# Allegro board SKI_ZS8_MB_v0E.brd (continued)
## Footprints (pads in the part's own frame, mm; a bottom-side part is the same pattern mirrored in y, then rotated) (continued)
BSH-030-01-L-D-A-TR-60P-LDH
  round 1.016 hole 1.016 unplated: (-10.063,-2.666) (10.063,-2.666)
  rect 0.279x2.261 smd: 1(-7.25,-2.864) 2(-6.75,-2.864) 3(-6.25,-2.864) 4(-5.75,-2.864) 5(-5.25,-2.864) 6(-4.75,-2.864) 7(-4.25,-2.864) 8(-3.75,-2.864) 9(-3.25,-2.864) 10(-2.75,-2.864) 11(-2.25,-2.864) 12(-1.75,-2.864) 13(-1.25,-2.864) 14(-0.75,-2.864) 15(-0.25,-2.864) 16(0.25,-2.864) 17(0.75,-2.864) 18(1.25,-2.864) 19(1.75,-2.864) 20(2.25,-2.864) 21(2.75,-2.864) 22(3.25,-2.864) 23(3.75,-2.864) 24(4.25,-2.864) 25(4.75,-2.864) 26(5.25,-2.864) 27(5.75,-2.864) 28(6.25,-2.864) 29(6.75,-2.864) 30(7.25,-2.864) 31(7.25,2.864) 32(6.75,2.864) 33(6.25,2.864) 34(5.75,2.864) 35(5.25,2.864) 36(4.75,2.864) 37(4.25,2.864) 38(3.75,2.864) 39(3.25,2.864) 40(2.75,2.864) 41(2.25,2.864) 42(1.75,2.864) 43(1.25,2.864) 44(0.75,2.864) 45(0.25,2.864) 46(-0.25,2.864) 47(-0.75,2.864) 48(-1.25,2.864) 49(-1.75,2.864) 50(-2.25,2.864) 51(-2.75,2.864) 52(-3.25,2.864) 53(-3.75,2.864) 54(-4.25,2.864) 55(-4.75,2.864) 56(-5.25,2.864) 57(-5.75,2.864) 58(-6.25,2.864) 59(-6.75,2.864) 60(-7.25,2.864)
CC0402
  custom 0.12x0.12 smd: 1(0.39,0) 2(-0.39,0)
CC0603
  rect 0.813x0.711 smd: 1(0.737,0) 2(-0.737,0)
CC0805
  rect 0.94x1.346 smd: 1(0.895,0) 2(-0.895,0)
CC3528
  rect 2.032x2.413 smd: 1(1.6,0) 2(-1.6,0)
CC7343
  rect 2.413x2.819 smd: 1(-3.2,0) 2(3.2,0)
CHOKE-PCMC063T-3R3MN-SMT
  rect 1.854x3.505 smd: 1(-3.275,0) 2(3.275,0)
CHOKE-PCMC063T-R82MN-4P-SMT
  custom 0.591x0.591 smd: 1(-3.596,0) 2(3.596,0)
  rect 1.473x0.305 smd: 3(-2.452,0) 4(2.452,0)
D-DO-214AC
  rect 1.88x2.032 smd: 1(-2.1,0) 2(2.1,0)
DSM
  rect 1.016x0.508 smd: 1(-1.3,0) 2(1.321,0)
DSMV
  rect 1.016x0.762 smd: 1(-1.27,0) 2(1.27,0)
EMIPAD47X31-63X24-3P
  rect 1.6x0.61 smd: 1(-1.8,0) 3(1.8,0)
  rect 1.194x0.787 smd: 2(0,0)
EMIPAD63X56
  custom 0.358x0.358 smd: 1(0,0)
FILTER-MCM2012B900GBE-4P
  rect 0.762x0.406 smd: 1(-0.925,0.4) 2(0.925,0.4) 3(0.925,-0.4) 4(-0.925,-0.4)
H-C87D87N
  round 2.21 hole 2.21 unplated: (0,0)
H-C150D150N
  round 3.81 hole 3.81 unplated: (0,0)
H-C217D142P2
  round 5.512 hole 3.607: 1(0,0)
H-C236D102P2
  round 5.994 hole 2.591: 1(0,0)
H-O98X79D98X79N
  oval 2.489x2.007 hole 2.489x2.007 unplated: (0,0)
H-TC217BC165D165P2
  round 5.512 hole 4.191: 1(0,0)
H-TC236BC197D102P2
  round 5.994 hole 2.591: 1(0,0)
HDMI-C128F4-K1909-L-19P-SMT
  round 0.787 hole 0.559: 1(4.5,6.8) 2(4,5.3) 3(3.5,6.8) 4(3,5.3) 5(2.5,6.8) 6(2,5.3) 7(1.5,6.8) 8(1,5.3) 9(0.5,6.8) 10(0,5.3) 11(-0.5,6.8) 12(-1,5.3) 13(-1.5,6.8) 14(-2,5.3) 15(-2.5,6.8) 16(-3,5.3) 17(-3.5,6.8) 18(-4,5.3) 19(-4.5,6.8)
  oval 1.6x2.794 hole 1.092x2.311: 20(7.25,6.5) 22(-7.25,6.5)
  oval 1.6x1.905 hole 1.092x1.397: 21(8.75,0) 23(-8.75,0)
IMD
  rect 1.016x0.813 smd: 1(1.2,-1) 3(1.2,1) 4(-1.2,1) 6(-1.2,-1)
  rect 1.016x0.61 smd: 2(1.2,0) 5(-1.2,0)
LQFP128-16X16-4-1_6H
  rect 0.203x1.499 smd: 1(-6.2,-7.85) 2(-5.8,-7.85) 3(-5.4,-7.85) 4(-5,-7.85) 5(-4.6,-7.85) 6(-4.2,-7.85) 7(-3.8,-7.85) 8(-3.4,-7.85) 9(-3,-7.85) 10(-2.6,-7.85) 11(-2.2,-7.85) 12(-1.8,-7.85) 13(-1.4,-7.85) 14(-1,-7.85) 15(-0.6,-7.85) 16(-0.2,-7.85) 17(0.2,-7.85) 18(0.6,-7.85) 19(1,-7.85) 20(1.4,-7.85) 21(1.8,-7.85) 22(2.2,-7.85) 23(2.6,-7.85) 24(3,-7.85) 25(3.4,-7.85) 26(3.8,-7.85) 27(4.2,-7.85) 28(4.6,-7.85) 29(5,-7.85) 30(5.4,-7.85) 31(5.8,-7.85) 32(6.2,-7.85) 65(6.2,7.85) 66(5.8,7.85) 67(5.4,7.85) 68(5,7.85) 69(4.6,7.85) 70(4.2,7.85) 71(3.8,7.85) 72(3.4,7.85) 73(3,7.85) 74(2.6,7.85) 75(2.2,7.85) 76(1.8,7.85) 77(1.4,7.85) 78(1,7.85) 79(0.6,7.85) 80(0.2,7.85) 81(-0.2,7.85) 82(-0.6,7.85) 83(-1,7.85) 84(-1.4,7.85) 85(-1.8,7.85) 86(-2.2,7.85) 87(-2.6,7.85) 88(-3,7.85) 89(-3.4,7.85) 90(-3.8,7.85) 91(-4.2,7.85) 92(-4.6,7.85) 93(-5,7.85) 94(-5.4,7.85) 95(-5.8,7.85) 96(-6.2,7.85)
  rect 1.499x0.203 smd: 33(7.85,-6.2) 34(7.85,-5.8) 35(7.85,-5.4) 36(7.85,-5) 37(7.85,-4.6) 38(7.85,-4.2) 39(7.85,-3.8) 40(7.85,-3.4) 41(7.85,-3) 42(7.85,-2.6) 43(7.85,-2.2) 44(7.85,-1.8) 45(7.85,-1.4) 46(7.85,-1) 47(7.85,-0.6) 48(7.85,-0.2) 49(7.85,0.2) 50(7.85,0.6) 51(7.85,1) 52(7.85,1.4) 53(7.85,1.8) 54(7.85,2.2) 55(7.85,2.6) 56(7.85,3) 57(7.85,3.4) 58(7.85,3.8) 59(7.85,4.2) 60(7.85,4.6) 61(7.85,5) 62(7.85,5.4) 63(7.85,5.8) 64(7.85,6.2) 97(-7.85,6.2) 98(-7.85,5.8) 99(-7.85,5.4) 100(-7.85,5) 101(-7.85,4.6) 102(-7.85,4.2) 103(-7.85,3.8) 104(-7.85,3.4) 105(-7.85,3) 106(-7.85,2.6) 107(-7.85,2.2) 108(-7.85,1.8) 109(-7.85,1.4) 110(-7.85,1) 111(-7.85,0.6) 112(-7.85,0.2) 113(-7.85,-0.2) 114(-7.85,-0.6) 115(-7.85,-1) 116(-7.85,-1.4) 117(-7.85,-1.8) 118(-7.85,-2.2) 119(-7.85,-2.6) 120(-7.85,-3) 121(-7.85,-3.4) 122(-7.85,-3.8) 123(-7.85,-4.2) 124(-7.85,-4.6) 125(-7.85,-5) 126(-7.85,-5.4) 127(-7.85,-5.8) 128(-7.85,-6.2)
LVDS-50473-0200M-001-20P-L
  rect 0.254x1.092 smd: 1(-4.75,2.92) 2(-4.25,2.92) 3(-3.75,2.92) 4(-3.25,2.92) 5(-2.75,2.92) 6(-2.25,2.92) 7(-1.75,2.92) 8(-1.25,2.92) 9(-0.75,2.92) 10(-0.25,2.92) 11(0.25,2.92) 12(0.75,2.92) 13(1.25,2.92) 14(1.75,2.92) 15(2.25,2.92) 16(2.75,2.92) 17(3.25,2.92) 18(3.75,2.92) 19(4.25,2.92) 20(4.75,2.92)
  rect 0.559x1.092 smd: 21(-5.65,2.92) 22(5.65,2.92)
  rect 1.397x1.905 smd: 23(-7.85,0) 24(7.85,0)
LVDS-50473-0300M-V01-30P-L
  rect 0.254x1.092 smd: 1(-7.25,2.92) 2(-6.75,2.92) 3(-6.25,2.92) 4(-5.75,2.92) 5(-5.25,2.92) 6(-4.75,2.92) 7(-4.25,2.92) 8(-3.75,2.92) 9(-3.25,2.92) 10(-2.75,2.92) 11(-2.25,2.92) 12(-1.75,2.92) 13(-1.25,2.92) 14(-0.75,2.92) 15(-0.25,2.92) 16(0.25,2.92) 17(0.75,2.92) 18(1.25,2.92) 19(1.75,2.92) 20(2.25,2.92) 21(2.75,2.92) 22(3.25,2.92) 23(3.75,2.92) 24(4.25,2.92) 25(4.75,2.92) 26(5.25,2.92) 27(5.75,2.92) 28(6.25,2.92) 29(6.75,2.92) 30(7.25,2.92)
  rect 0.559x1.092 smd: 31(-8.15,2.92) 32(8.15,2.92)
  rect 1.397x1.905 smd: 33(-10.35,0) 34(10.35,0)
MINIPCI-SM3ZS067U215AE-75P-KE
  round 1.092 hole 1.092 unplated: (-10,0)
  round 1.6 hole 1.6 unplated: (10,0)
  rect 0.305x1.549 smd: 1(-9.25,5.225) 2(-9,-2.225) 3(-8.75,5.225) 4(-8.5,-2.225) 5(-8.25,5.225) 6(-8,-2.225) 7(-7.75,5.225) 8(-7.5,-2.225) 9(-7.25,5.225) 10(-7,-2.225) 11(-6.75,5.225) 12(-6.5,-2.225) 13(-6.25,5.225) 14(-6,-2.225) 15(-5.75,5.225) 16(-5.5,-2.225) 17(-5.25,5.225) 18(-5,-2.225) 19(-4.75,5.225) 20(-4.5,-2.225) 21(-4.25,5.225) 22(-4,-2.225) 23(-3.75,5.225) 32(-1.5,-2.225) 33(-1.25,5.225) 34(-1,-2.225) 35(-0.75,5.225) 36(-0.5,-2.225) 37(-0.25,5.225) 38(0,-2.225) 39(0.25,5.225) 40(0.5,-2.225) 41(0.75,5.225) 42(1,-2.225) 43(1.25,5.225) 44(1.5,-2.225) 45(1.75,5.225) 46(2,-2.225) 47(2.25,5.225) 48(2.5,-2.225) 49(2.75,5.225) 50(3,-2.225) 51(3.25,5.225) 52(3.5,-2.225) 53(3.75,5.225) 54(4,-2.225) 55(4.25,5.225) 56(4.5,-2.225) 57(4.75,5.225) 58(5,-2.225) 59(5.25,5.225) 60(5.5,-2.225) 61(5.75,5.225) 62(6,-2.225) 63(6.25,5.225) 64(6.5,-2.225) 65(6.75,5.225) 66(7,-2.225) 67(7.25,5.225) 68(7.5,-2.225) 69(7.75,5.225) 70(8,-2.225) 71(8.25,5.225) 72(8.5,-2.225) 73(8.75,5.225) 74(9,-2.225) 75(9.25,5.225)
  rect 1.194x2.743 smd: 76(-10.35,4.5) 77(10.35,4.5)
MSOP8-4_9-65
  rect 0.406x1.448 smd: 1(-0.975,-2.325) 2(-0.325,-2.325) 3(0.325,-2.325) 4(0.975,-2.325) 5(0.975,2.325) 6(0.325,2.325) 7(-0.325,2.325) 8(-0.975,2.325)
NGFF-80159-2181-75P-KM
  round 1.092 hole 1.092 unplated: (-11,0)
  round 1.6 hole 1.6 unplated: (11,0)
  round 0.762 hole 0.508: 1(9.25,-0.09) 3(8.75,-0.89) 5(8.25,-0.09) 7(7.75,-0.89) 9(7.25,-0.09) 11(6.75,-0.89) 13(6.25,-0.09) 15(5.75,-0.89) 17(5.25,-0.09) 19(4.75,-0.89) 21(4.25,-0.09) 23(3.75,-0.89) 25(3.25,-0.09) 27(2.75,-0.89) 29(2.25,-0.09) 31(1.75,-0.89) 33(1.25,-0.09) 35(0.75,-0.89) 37(0.25,-0.09) 39(-0.25,-0.89) 41(-0.75,-0.09) 43(-1.25,-0.89) 45(-1.75,-0.09) 47(-2.25,-0.89) 49(-2.75,-0.09) 51(-3.25,-0.89) 53(-3.75,-0.09) 55(-4.25,-0.89) 57(-4.75,-0.09) 67(-7.25,-0.89) 69(-7.75,-0.09) 71(-8.25,-0.89) 73(-8.75,-0.09) 75(-9.25,-0.89)
  rect 0.305x1.499 smd: 2(9,1.7) 4(8.5,1.7) 6(8,1.7) 8(7.5,1.7) 10(7,1.7) 12(6.5,1.7) 14(6,1.7) 16(5.5,1.7) 18(5,1.7) 20(4.5,1.7) 22(4,1.7) 24(3.5,1.7) 26(3,1.7) 28(2.5,1.7) 30(2,1.7) 32(1.5,1.7) 34(1,1.7) 36(0.5,1.7) 38(0,1.7) 40(-0.5,1.7) 42(-1,1.7) 44(-1.5,1.7) 46(-2,1.7) 48(-2.5,1.7) 50(-3,1.7) 52(-3.5,1.7) 54(-4,1.7) 56(-4.5,1.7) 58(-5,1.7) 68(-7.5,1.7) 70(-8,1.7) 72(-8.5,1.7) 74(-9,1.7)
  oval 0.889x1.956 hole 0.508x1.753: 76(11.25,-4.05) 77(-11.25,-4.05)
O-SKI-1
  round 5.994 hole 2.591: 1(0,0)
  oval 0.61x2.388 hole 0.61x2.388: 2(-9.55,-2.085) 3(23.25,-2.085)
PHJK-2SJ3095-033111F-6P
  oval 0.991x1.803 hole 0.61x1.397: 1(-4.85,7.01) 2(4.7,1.51) 3(-4.85,-0.79) 4(4.7,-1.39) 5(4.7,7.01) 6(4.7,4.26) 7(-4.85,2.91)
POWER-6_5-1_84-3P
  rect 0.787x1.397 smd: 1(3.532,0.9) 2(3.532,-0.9)
  rect 4.699x3.607 smd: 3(-0.338,0)
PVQFN20-3_5X3_5-5-25P
  rect 0.279x0.838 smd: 1(-1,-1.725) 2(-0.5,-1.725) 3(0,-1.725) 4(0.5,-1.725) 5(1,-1.725) 11(1,1.725) 12(0.5,1.725) 13(0,1.725) 14(-0.5,1.725) 15(-1,1.725)
  rect 0.838x0.279 smd: 6(1.725,-1) 7(1.725,-0.5) 8(1.725,0) 9(1.725,0.5) 10(1.725,1) 16(-1.725,1) 17(-1.725,0.5) 18(-1.725,0) 19(-1.725,-0.5) 20(-1.725,-1)
  rect 2.057x2.057 smd: 21(0,0)
  round 0.61 hole 0.305: 22(-0.5,-0.5) 23(0.5,-0.5) 24(0.5,0.5) 25(-0.5,0.5)
QFN14-3X3-4-16P
  rect 1.092x0.203 smd: 1(-1.25,0.525) 2(-1.25,-0.175) 8(1.25,-0.525) 9(1.25,0.175)
  rect 0.203x0.711 smd: 3(-0.8,-1.45) 4(-0.4,-1.45) 5(0,-1.45) 6(0.4,-1.45) 7(0.8,-1.45) 10(0.8,1.45) 11(0.4,1.45) 12(0,1.45) 13(-0.4,1.45) 14(-0.8,1.45)
  rect 0.66x0.203 smd: 15(0,0.165) 16(0,-0.435)
QFN20-3X3-4-26P
  rect 0.787x0.203 smd: 1(-1.5,0.8) 2(-1.5,0.4) 3(-1.5,0) 4(-1.5,-0.4) 5(-1.5,-0.8) 11(1.5,-0.8) 12(1.5,-0.4) 13(1.5,0) 14(1.5,0.4) 15(1.5,0.8)
  rect 0.203x0.787 smd: 6(-0.8,-1.5) 7(-0.4,-1.5) 8(0,-1.5) 9(0.4,-1.5) 10(0.8,-1.5) 16(0.8,1.5) 17(0.4,1.5) 18(0,1.5) 19(-0.4,1.5) 20(-0.8,1.5)
  rect 1.803x1.803 smd: 21(0,0)
  round 0.508 hole 0.305: 22(-0.5,0.5) 23(-0.5,-0.5) 24(0.5,-0.5) 25(0.5,0.5) 26(0,0)
QFN32-4X4-4-42P-1H
  custom 0.05x0.05 smd: 1(-2,1.4) 2(-2,1) 3(-2,0.6) 4(-2,0.2) 5(-2,-0.2) 6(-2,-0.6) 7(-2,-1) 8(-2,-1.4) 9(-1.4,-2) 10(-1,-2) 11(-0.6,-2) 12(-0.2,-2) 13(0.2,-2) 14(0.6,-2) 15(1,-2) 16(1.4,-2) 17(2,-1.4) 18(2,-1) 19(2,-0.6) 20(2,-0.2) 21(2,0.2) 22(2,0.6) 23(2,1) 24(2,1.4) 25(1.4,2) 26(1,2) 27(0.6,2) 28(0.2,2) 29(-0.2,2) 30(-0.6,2) 31(-1,2) 32(-1.4,2)
  rect 2.794x2.794 smd: 33(0,0)
  round 0.61 hole 0.305: 34(-1,1) 35(-1,0) 36(-1,-1) 37(0,-1) 38(1,-1) 39(1,0) 40(1,1) 41(0,1) 42(0,0)
QFN48-6X6-4-49P-ALC280
  rect 0.203x0.991 smd: 1(-2.2,-3.1) 2(-1.8,-3.1) 3(-1.4,-3.1) 4(-1,-3.1) 5(-0.6,-3.1) 6(-0.2,-3.1) 7(0.2,-3.1) 8(0.6,-3.1) 9(1,-3.1) 10(1.4,-3.1) 11(1.8,-3.1) 12(2.2,-3.1) 25(2.2,3.1) 26(1.8,3.1) 27(1.4,3.1) 28(1,3.1) 29(0.6,3.1) 30(0.2,3.1) 31(-0.2,3.1) 32(-0.6,3.1) 33(-1,3.1) 34(-1.4,3.1) 35(-1.8,3.1) 36(-2.2,3.1)
  rect 0.991x0.203 smd: 13(3.1,-2.2) 14(3.1,-1.8) 15(3.1,-1.4) 16(3.1,-1) 17(3.1,-0.6) 18(3.1,-0.2) 19(3.1,0.2) 20(3.1,0.6) 21(3.1,1) 22(3.1,1.4) 23(3.1,1.8) 24(3.1,2.2) 37(-3.1,2.2) 38(-3.1,1.8) 39(-3.1,1.4) 40(-3.1,1) 41(-3.1,0.6) 42(-3.1,0.2) 43(-3.1,-0.2) 44(-3.1,-0.6) 45(-3.1,-1) 46(-3.1,-1.4) 47(-3.1,-1.8) 48(-3.1,-2.2)
  rect 4.394x4.394 smd: 49(0,0)
RC0402
  custom 0.12x0.12 smd: 1(0.39,0) 2(-0.39,0)
RC0603
  rect 0.813x0.711 smd: 1(0.737,0) 2(-0.737,0)
RC0805
  rect 0.94x1.346 smd: 1(0.895,0) 2(-0.895,0)
RC1206
  rect 1.6x1.6 smd: 1(1.702,0) 2(-1.702,0)
RC3216
  rect 3.2x0.94 smd: 1(0,0.825) 2(0,-0.825)
SC70-2_1-65-6P
  rect 1.27x0.279 smd: 1(1.02,-0.65) 2(1.02,0) 3(1.02,0.65) 4(-1.02,0.65) 5(-1.02,0) 6(-1.02,-0.65)
SHORT0402
  rect 0.648x0.5 smd: 1(-0.39,0) 2(0.39,0)
SHORT0603
  rect 1.168x0.711 smd: 1(0.737,0) 2(-0.737,0)
SHORT0805
  rect 1.397x1.346 smd: 1(0.895,0) 2(-0.895,0)
SHORT3720
  rect 3.759x1.537 smd: 1(0,1.008) 2(0,-1.008)
SO-8FL-5P-OA
  rect 0.991x0.762 smd: 1(3.73,-1.905) 2(3.73,-0.635) 3(3.73,0.635) 4(3.73,1.905)
  custom 1.132x1.132 smd: 5(0,0)
SOIC8-6-1_27
  rect 0.533x1.753 smd: 1(-1.905,-2.73) 2(-0.635,-2.73) 3(0.635,-2.73) 4(1.905,-2.73) 5(1.905,2.73) 6(0.635,2.73) 7(-0.635,2.73) 8(-1.905,2.73)
SOIC8-7_9-1_27-2_16H
  rect 0.533x1.549 smd: 1(-1.905,-3.775) 2(-0.635,-3.775) 3(0.635,-3.775) 4(1.905,-3.775) 5(1.905,3.775) 6(0.635,3.775) 7(-0.635,3.775) 8(-1.905,3.775)
SOLDERJUMPER-2
  custom 0.381x0.381 smd: 1(-1.016,0) 2(1.016,0)
SON8-4_5X3_5-5-9P-SMT
  custom 0.05x0.05 smd: 1(-1.6,-1.6) 2(-1.2,-1.6) 3(-0.8,-1.6) 6(-0.8,1.6) 7(-1.2,1.6) 8(-1.6,1.6)
  custom 0.188x0.188 smd: 4(0.6,-1.6) 5(0.6,1.6)
  rect 4.039x2.21 smd: 9(0,0)
SON10-3X3-5-16P
  rect 0.279x0.838 smd: 1(-1,-1.475) 2(-0.5,-1.475) 3(0,-1.475) 4(0.5,-1.475) 5(1,-1.475) 6(1,1.475) 7(0.5,1.475) 8(0,1.475) 9(-0.5,1.475) 10(-1,1.475)
  custom 0.413x0.413 smd: 11(0,0)
  round 0.61 hole 0.305: 12(-0.75,-0.5) 13(0.75,-0.5) 14(0.75,0.5) 15(-0.75,0.5) 16(0,0)
SOP8-6-1_27-9P
  rect 0.533x1.727 smd: 1(-1.905,-2.73) 2(-0.635,-2.73) 3(0.635,-2.73) 4(1.905,-2.73) 5(1.905,2.73) 6(0.635,2.73) 7(-0.635,2.73) 8(-1.905,2.73)
  rect 3.302x2.794 smd: 9(0,0)
SOT23-2_8-95-6P
  rect 1.346x0.508 smd: 1(1.325,-0.95) 2(1.325,0) 3(1.325,0.95) 4(-1.325,0.95) 5(-1.325,0) 6(-1.325,-0.95)
SOT23-6-2_8-95-6P
  rect 1.194x0.508 smd: 1(1.5,-0.95) 2(1.5,0) 3(1.5,0.95) 4(-1.5,0.95) 5(-1.5,0) 6(-1.5,-0.95)
SOT23_123-2_8-1_9
  rect 1.092x0.533 smd: 1(1.45,-0.95) 2(1.45,0.95) 3(-1.45,0)
SOT23_213-3_3-2
  rect 1.27x1.016 smd: 1(1.016,1.016) 2(1.016,-1.016) 3(-1.016,0)
SOT353-1-2_125-65-5P
  rect 1.245x0.279 smd: 1(1.045,-0.65) 2(1.045,0) 3(1.045,0.65) 4(-1.045,0.65) 5(-1.045,-0.65)
SSOP5-P-A-TOSHIBA-B
  rect 1.067x0.305 smd: 1(0.85,-0.65) 2(0.85,0) 3(0.85,0.65) 4(-0.85,0.65) 5(-0.85,-0.65)
SW-NTC017-BB1J-X160T-4P-SMT
  rect 0.61x0.991 smd: 1(-1.85,2.2) 2(1.85,2.2) 3(-1.85,-2.2) 4(1.85,-2.2)
  rect 0.457x1.499 smd: 5(-2.525,0) 6(2.525,0)
SW-TC901-AA1G-A160T-6P
  rect 0.991x1.702 smd: 1(-1.8,3.15) 2(1.8,3.15) 3(-1.8,-3.15) 4(1.8,-3.15)
  rect 0.457x0.991 smd: 5(-2.525,0) 6(2.525,0)
TDFN8-2X2-5-9P-MAX14566
  rect 0.305x0.711 smd: 1(-0.75,-0.99) 2(-0.25,-0.99) 3(0.25,-0.99) 4(0.75,-0.99) 5(0.75,0.99) 6(0.25,0.99) 7(-0.25,0.99) 8(-0.75,0.99)
  rect 1.295x0.711 smd: 9(0,0)
TP2675
  round 0.66 smd: 1(0,0)
TSSOP28-6_4-65-SLB9635TT
  rect 0.406x1.295 smd: 1(-4.225,-3.05) 2(-3.575,-3.05) 3(-2.925,-3.05) 4(-2.275,-3.05) 5(-1.625,-3.05) 6(-0.975,-3.05) 7(-0.325,-3.05) 8(0.325,-3.05) 9(0.975,-3.05) 10(1.625,-3.05) 11(2.275,-3.05) 12(2.925,-3.05) 13(3.575,-3.05) 14(4.225,-3.05) 15(4.225,3.05) 16(3.575,3.05) 17(2.925,3.05) 18(2.275,3.05) 19(1.625,3.05) 20(0.975,3.05) 21(0.325,3.05) 22(-0.325,3.05) 23(-0.975,3.05) 24(-1.625,3.05) 25(-2.275,3.05) 26(-2.925,3.05) 27(-3.575,3.05) 28(-4.225,3.05)
UMT_213-3-1_3
  rect 1.016x0.762 smd: 1(0.991,0.66) 2(0.991,-0.66) 3(-0.991,0)
unnamed#2
  round 1.016 smd: 1(0,0)
USB-53063-00902-001-9P-SMT
  round 1.118 hole 0.813: 1(-3.5,7.73) 2(-1,7.73) 3(1,7.73) 4(3.5,7.73) 5(4,9.23) 6(2,9.23) 7(0,9.23) 8(-2,9.23) 9(-4,9.23)
  oval 1.626x2.515 hole 0.61x1.499: 10(-7.85,0) 11(7.85,0)
  oval 1.727x3.327 hole 0.711x2.311: 12(7.85,6.8) 13(-7.85,6.8)
VQFN14-3_5X3_5-5-15P
  rect 0.838x0.279 smd: 1(-1.725,-0.75) 7(1.725,-0.75) 8(1.725,0.75) 14(-1.725,0.75)
  rect 0.279x0.838 smd: 2(-1,-1.725) 3(-0.5,-1.725) 4(0,-1.725) 5(0.5,-1.725) 6(1,-1.725) 9(1,1.725) 10(0.5,1.725) 11(0,1.725) 12(-0.5,1.725) 13(-1,1.725)
  rect 2.057x2.057 smd: 15(0,0)
WDFN5-3_05X3_05-65
  rect 0.66x0.432 smd: 1(1.385,-0.975) 2(1.385,-0.325) 3(1.385,0.325) 4(1.385,0.975)
  custom 0.575x0.575 smd: 5(-0.735,0)
XTL-3_2X1_5-2_5-0_8H
  rect 0.991x1.803 smd: 1(-1.25,0) 2(1.25,0)
XTL-3_2X2_5-2_2X1_7-0_8H
  rect 1.397x1.194 smd: 1(-1.1,-0.85) 2(1.1,-0.85) 3(1.1,0.85) 4(-1.1,0.85)

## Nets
2.469V: PR133.2 PR134.1 PU9.3
3VPCU_AGND: PC45.1 PC50.1 PC97.1 PR35.1 PR142.1 PU3.14
3VPCU_VIN: JP5.1 PC53.1 PC61.1 PC102.2 PC103.1 PC106.1 PR45.1 PU3.1
5VPCU_AGND: PC44.1 PC99.1 PR26.2 PR139.2 PR140.1 PU2.14
5VPCU_VIN: JP4.1 PC51.1 PC57.2 PC98.1 PC101.1 PC105.1 PR41.1 PU2.1
51211V_DRVH: PQ4.4 PU5.9
51211V_DRVL: PQ5.4 PU5.6
51211V_EN: PR58.2 PR147.2 PU5.3
51211V_FB: PR148.1 PR149.2 PU5.4
51211V_SW: PC62.2 PL5.1 PQ4.1 PQ4.2 PQ4.3 PQ5.5 PR136.1 PU5.8
51211V_TRIP: PR57.2 PU5.2
51211V_TST: PR59.2 PU5.5
51211V_VBST: PR51.2 PU5.10
+1.2VSUS_SRC: JP2.1 PC29.2 PC30.2 PC31.2 PC35.2 PC36.2 PC37.2 PC38.2 PC58.2 PL2.2 PU4.2 PU4.9
+1V2_SUS: C58.1 C77.1 C78.1 C79.1 C81.1 C82.1 C84.1 C88.1 C89.1 C270.1 C271.1 C272.1 C273.1 C274.1 C276.1 C277.1 C278.1 C279.1 C280.1 C282.1 C284.1 C285.1 C289.1 C290.1 C292.1 C294.1 C300.1 C301.1 C302.1 C303.1 C305.1 C306.1 C307.1 C308.1 C309.1 C311.1 C313.1 C315.1 C318.1 C319.1 C320.1 C321.1 C322.1 C323.1 C324.1 C325.1 C326.1 C327.1 C328.1 C329.1 C330.1 C331.1 C332.1 C333.1 C334.1 C338.1 C339.1 C341.1 C342.1 C343.1 C344.1 C345.1 C348.1 C350.1 C351.1 C353.1 C354.1 C357.1 C358.1 C359.1 C360.1 JP2.2 R461.1 R462.1 R476.2 R479.2 R524.2 U7.5 U11.A8 U11.A9 U11.A11 U11.C12 U11.D4 U11.D5 U11.D6 U11.E8 U11.E12 U11.F2 U11.G2 U11.G5 U11.G12 U11.H3 U11.H5 U11.H6 U11.H8 U11.H9 U11.H11 U11.H12 U11.J5 U11.J6 U11.J9 U11.J10 U11.K5 U11.K6 U11.K8 U11.K11 U11.K12 U11.L2 U11.L5 U11.L12 U11.M2 U11.N8 U11.N12 U11.P4 U11.P5 U11.P6 U11.R12 U11.U8 U11.U9 U11.U11 U12.A8 U12.A9 U12.A11 U12.C12 U12.D4 U12.D5 U12.D6 U12.E8 U12.E12 U12.F2 U12.G2 U12.G5 U12.G12 U12.H3 U12.H5 U12.H6 U12.H8 U12.H9 U12.H11 U12.H12 U12.J5 U12.J6 U12.J9 U12.J10 U12.K5 U12.K6 U12.K8 U12.K11 U12.K12 U12.L2 U12.L5 U12.L12 U12.M2 U12.N8 U12.N12 U12.P4 U12.P5 U12.P6 U12.R12 U12.U8 U12.U9 U12.U11 U13.A8 U13.A9 U13.A11 U13.C12 U13.D4 U13.D5 U13.D6 U13.E8 U13.E12 U13.F2 U13.G2 U13.G5 U13.G12 U13.H3 U13.H5 U13.H6 U13.H8 U13.H9 U13.H11 U13.H12 U13.J5 U13.J6 U13.J9 U13.J10 U13.K5 U13.K6 U13.K8 U13.K11 U13.K12 U13.L2 U13.L5 U13.L12 U13.M2 U13.N8 U13.N12 U13.P4 U13.P5 U13.P6 U13.R12 U13.U8 U13.U9 U13.U11 U14.A8 U14.A9 U14.A11 U14.C12 U14.D4 U14.D5 U14.D6 U14.E8 U14.E12 U14.F2 U14.G2 U14.G5 U14.G12 U14.H3 U14.H5 U14.H6 U14.H8 U14.H9 U14.H11 U14.H12 U14.J5 U14.J6 U14.J9 U14.J10 U14.K5 U14.K6 U14.K8 U14.K11 U14.K12 U14.L2 U14.L5 U14.L12 U14.M2 U14.N8 U14.N12 U14.P4 U14.P5 U14.P6 U14.R12 U14.U8 U14.U9 U14.U11
+1V2_SUS_VDDQ: C223.1 C224.1 C225.1 C226.1 C227.1 C232.1 C244.1 C246.1 C252.1 C253.1 R461.2 R462.2 U6.AH26 U6.AJ31 U6.AJ33 U6.AJ37 U6.AN33 U6.AP43 U6.AR48 U6.AY35 U6.AY40 U6.AY44 U6.AY50
+1V05: C1.2 L3.1 L4.1 L5.1 PC11.1 PQ28.1 PQ28.2 PQ28.3 PR8.1 PR102.1 PR115.1 PR116.1 PR117.1 PR131.2 R1.1 R10.1 R11.2 R36.2 R339.2 R366.2 R402.1 R404.1 R405.1 R434.2 U1.5
+1V5: PC83.1 PR120.1 PU8.6 R317.2 R333.1
+1V5_ADO_AVDD2: C396.1 C398.1 R317.1 U16.40
+1V05_AIDLE: C194.1 R10.2 U6.N8 U6.P9
+1V05_APLLOPI: C3.1 C4.1 C205.1 L4.2 U6.AA21 U6.W21
+1V05_ASATA3PLL: C8.1 C13.1 C22.1 L1.2 R336.1 R337.2 U6.B11
+1V05_AUSB3PLL: C9.1 C14.1 C23.1 L2.2 R43.2 R44.1 U6.B18
+1V05_AXCK_DCB: C5.1 C6.1 C187.1 L5.2 U6.J18 U6.K19
+1V05_AXCK_LCPLL: C10.1 C15.1 C21.1 L3.2 R342.1 U6.A20
+1V05_CORE_PCH: C165.1 C174.1 C221.1 R11.1 U6.AE8 U6.AF22 U6.H11 U6.H15 U6.J11
+1V05_DCPSUS1: C212.1 R392.2 U6.AD8 U6.AD10
+1V05_DCPSUS2: C220.1 R401.1 U6.AH13
+1V05_DCPSUS3: C166.1 C175.1 R329.1 U6.J13
+1V05_DCPSUS4: C211.1 R386.2 U6.AB8
+1V05_S5: JP9.2 PQ26.5 PQ28.5 R54.1 R122.1 R123.1 R124.1 R125.1 R329.2 R386.1 R392.1 R401.2
+1V05_SRC: JP9.1 PC23.1 PC32.2 PL5.2 PR149.1
+1V05_VCCASW: C242.1 C243.1 R434.1 U6.AE9 U6.AF9 U6.AG8
+1V05_VCCASW_1: R405.2 U6.AG14
+1V05_VCCASW_2: R404.2 U6.AG13
+1V5_VCCATS: R333.2 U6.J15
+1V05_VCCCLK1: C178.1 R339.1 U6.J17
+1V05_VCCCLK2: C193.1 R366.1 U6.R21 U6.T21
+1V05_VCCST: C11.1 C207.1 Q1.3 R1.2 R8.1 R12.2 R17.2 R30.1 R42.2 R69.2 R78.1 R84.1 U2.5 U6.AC22 U6.AE22 U6.AE23
+1V05_VCCUSBCORE: C222.1 R402.2 U6.AG16 U6.AG17
+1V05_VIN: JP6.1 PC49.2 PC52.1 PQ4.5
+1V05DX_MODPHY: C173.1 C180.1 C192.1 L1.1 L2.1 PQ26.1 PQ26.2 PQ26.3 PR130.1 PR131.1 U6.K9 U6.L10 U6.M9
+1V8_SUS: C90.1 C91.1 C92.1 C95.1 C98.1 C101.1 C335.1 C336.1 C346.1 C352.1 C355.1 C356.1 PR175.1 U11.A3 U11.A4 U11.A5 U11.A6 U11.A10 U11.U3 U11.U4 U11.U5 U11.U6 U11.U10 U12.A3 U12.A4 U12.A5 U12.A6 U12.A10 U12.U3 U12.U4 U12.U5 U12.U6 U12.U10 U13.A3 U13.A4 U13.A5 U13.A6 U13.A10 U13.U3 U13.U4 U13.U5 U13.U6 U13.U10 U14.A3 U14.A4 U14.A5 U14.A6 U14.A10 U14.U3 U14.U4 U14.U5 U14.U6 U14.U10
+1V8_SUS_C: PC118.1 PR62.1 PR175.2 PU10.6
+3V3: C12.1 C25.1 C71.1 C120.1 C137.1 C139.1 C233.1 C371.1 C405.1 C406.1 CN12.8 CN12.9 CN12.10 CN14.9 CN14.10 PQ25.1 PQ25.2 PQ25.3 PR42.2 PR56.2 PR64.2 PR92.2 PR95.2 PR99.2 PR101.1 PR125.1 PR127.2 PR152.2 Q6.2 Q7.2 Q8.2 Q8.5 Q9.2 Q10.2 Q10.5 Q17.2 Q17.5 Q18.2 Q20.2 Q21.2 Q25.2 Q25.5 R2.1 R14.2 R15.2 R18.1 R19.1 R20.2 R21.1 R22.1 R24.1 R25.1 R46.1 R47.1 R48.1 R49.1 R50.1 R51.1 R52.2 R53.2 R56.1 R60.1 R61.1 R62.2 R63.1 R64.2 R65.2 R67.2 R70.1 R72.1 R74.2 R76.2 R80.1 R81.1 R82.1 R87.1 R88.2 R90.2 R93.2 R95.1 R97.1 R99.2 R121.2 R128.1 R129.1 R131.2 R157.2 R165.1 R210.2 R226.2 R228.1 R290.2 R294.2 R330.1 R332.1 R334.1 R343.2 R344.1 R345.2 R346.1 R347.1 R351.1 R352.1 R353.1 R355.1 R356.1 R357.1 R361.1 R362.1 R365.1 R368.2 R369.2 R370.2 R371.1 R372.1 R374.1 R375.2 R377.1 R378.1 R382.2 R384.1 R387.2 R388.2 R396.1 R398.2 R420.2 R430.1 R431.1 R432.1 R435.1 R485.1 R525.2 R527.2 R529.2 R552.1 R557.2 R559.1 R574.2 R579.2 R783.1 U4.14 U5.4 U5.6 U9.8 U18.5
+3V3_ADO: C381.1 C383.1 C385.1 C386.1 C390.1 R310.1 R557.1 U16.1 U16.9 U16.36
+3V3_CCD: C43.1 C44.1 CN7.3 R90.1
+3V3_DMIC: C404.1 CN17.1 R574.1
+3V3_EC: C100.1 R228.2 U23.11
+3V3_PCU: C24.1 C150.1 C153.1 C265.1 CN18.1 D6.1 D32.1 HE1.1 JP8.2 PC81.2 PC82.1 PC114.1 PC117.2 PC126.1 PQ12.3 PQ25.5 PQ27.3 PR44.1 PR69.2 PR155.2 PR156.2 PR160.2 PR166.2 PR167.2 PR170.2 PU6.5 PU8.3 PU10.3 R40.2 R45.2 R136.1 R194.1 R196.1 R203.2 R214.2 R408.2 R409.1 R417.1 R427.1 R428.1 R452.1 R455.1 R490.1 R492.1 R506.1 R509.2 R510.2 R517.2 RP1.5 RP1.10 U21.5
+3V3_PCU_EC: C83.1 C86.1 C87.1 C96.1 C124.1 C138.1 L14.2 L19.1 R203.1 R208.1 U23.26 U23.50 U23.92 U23.114 U23.121
+3V3_PCU_ECAVCC: C370.1 L19.2 U23.74
+3V3_PCU_ECPLL: C293.2 L14.1 U23.127
+3V3_PCU_ECVBAT: C93.1 R208.2 U23.3
+3V3_RTC: C247.1 C250.1 C255.1 C264.1 D7.3 R174.2 R178.2 R179.2 R459.2 R465.2 U6.AG10
+3V3_S5: C2.1 C73.1 C159.1 C162.1 C248.1 CN18.2 PQ27.1 PR54.1 PR97.2 PR105.2 Q11.2 Q11.5 Q13.1 Q19.1 R5.1 R79.2 R98.1 R113.1 R114.1 R116.1 R126.1 R127.1 R130.1 R132.1 R134.2 R140.2 R141.1 R144.1 R145.1 R146.1 R148.1 R151.1 R153.1 R155.1 R156.1 R160.1 R164.1 R167.1 R298.2 R325.1 R381.1 R383.1 R390.1 R391.1 R399.1 R403.2 R406.1 R407.2 R410.1 R412.1 R418.1 R425.1 R429.1 R445.1 R450.1 R451.1 R453.2 R458.2 R463.2 R511.2 R512.2 R775.2 R776.1 R777.1 R778.1 U3.5 U20.5
+3V3_S5_DEEP: C210.1 C213.1 Q13.3 R195.1 R458.1 U6.AA9 U6.AC9 U6.AE20 U6.AE21 U6.AH11
+3V3_S5_HDA: C245.1 R453.1 U6.AH14
+3V3_S5_PSPI: C206.1 R381.2 U6.Y8
+3V3_S5_SPI: C254.1 R177.2 R463.1 R478.2 R482.1 U19.8
+3V3_SATA_N0: C131.1 C132.1 C156.1 C157.1 C409.1 C410.1 CN13.2 CN13.4 CN13.70 CN13.72 CN13.74 R308.2 R579.1
+3V3_SATA_N0_N: CN13.12 CN13.14 CN13.16 CN13.18 R308.1
+3V3_SATA_N1: C74.1 C75.1 C263.1 C347.1 C365.1 C368.1 CN10.2 CN10.4 CN10.70 CN10.72 CN10.74 R227.1 R290.1 R483.2
+3V3_SATA_N1_N: CN10.12 CN10.14 CN10.16 CN10.18 R483.1
+3V3_SER: C31.1 C32.1 CN7.1 CN7.2 Q19.3 R67.1 R787.2 R788.2
+3V3_SUS: PQ12.1 PR46.1 R303.2 R323.1 R779.1
+3V3_TPM: C366.1 C367.1 C376.1 C378.1 R294.1 R299.1 U15.10 U15.19 U15.24
+3V3_TPM_VSB: C375.1 C380.1 R298.1 R303.1 U15.5
+3V3_VCCPCORE: C195.1 R382.1 U6.V8 U6.W9
+3V3_VCCPTS: C179.1 R332.2 U6.K14 U6.K16
+3V3_VCCSDIO: C196.1 R396.2 U6.T9 U6.U8
+3V3_WLAN: C62.1 C63.1 C236.1 C238.1 C241.1 CN9.2 CN9.4 CN9.72 CN9.74 Q22.2 R435.2 R474.2
+3V_LDO: PC97.2 PR31.2 PU3.6
+5V: C114.1 C151.1 C152.1 C154.1 C155.1 C369.1 CN12.6 CN12.7 D2.2 D3.2 L17.1 PQ31.1 PR93.1 Q3.3 R101.2 R158.1 R159.1 R313.2 R314.2
+5V_ADO_AVDD: C374.1 C379.1 L17.2 U16.26
+5V_ADO_PVDD1: C388.1 C393.1 R313.1 U16.41
+5V_ADO_PVDD2: C389.1 C394.1 R314.1 U16.46
+5V_FAN: CN3.1 R159.2
+5V_HDMI: C7.1 CN2.18 D1.1 Q3.1
+5V_PCU: C64.1 C240.1 JP7.2 PC40.2 PC63.2 PC78.2 PC116.2 PQ30.5 PQ31.3 PU4.12 PU5.7 PU8.4 PU10.4 R433.2 U8.2 U8.3 U17.5
+5V_PCU_USB3_P0: C60.1 C61.1 CN4.1 U8.6 U8.7 U8.8
+5V_S5: C80.1 C99.1 PC12.1 PQ30.1 PQ30.2 PQ30.3 PR9.2 PR50.1 PU1.2 R142.1 U10.2 U10.3 U22.2 U22.3
+5V_S5_USB2: C363.1 C364.1 CN12.1 CN12.2 CN12.3 CN12.4 CN12.5 U22.6 U22.7 U22.8
+5V_S5_USB3_P1: C76.1 C85.1 CN5.1 U10.6 U10.7 U10.8
+5V_TS: C49.1 C50.1 CN7.4 R101.1
+15V: PR38.1 PR53.1 PR113.1 PR118.1 PR145.1
+VCC_RTC: BT1.1 R501.2
+VCCIN: C167.1 C168.1 C169.1 C170.1 C171.1 C172.1 C181.1 C182.1 C183.1 C184.1 C185.1 C186.1 C188.1 C189.1 C190.1 C191.1 C197.1 C198.1 C199.1 C200.1 C201.1 C202.1 C203.1 C204.1 C208.1 C209.1 C214.1 C215.1 C216.1 C217.1 PC14.1 PC15.1 PC16.1 PC17.1 PL1.2 PR104.2 R38.2 U6.AB57 U6.AD57 U6.AG57 U6.C24 U6.C28 U6.C32 U6.C36 U6.C40 U6.C44 U6.C48 U6.C52 U6.C56 U6.E23 U6.E25 U6.E27 U6.E29 U6.E31 U6.E33 U6.E35 U6.E37 U6.E39 U6.E41 U6.E43 U6.E45 U6.E47 U6.E49 U6.E51 U6.E53 U6.E55 U6.E57 U6.F24 U6.F28 U6.F32 U6.F36 U6.F40 U6.F44 U6.F48 U6.F52 U6.F56 U6.F59 U6.G23 U6.G25 U6.G27 U6.G29 U6.G31 U6.G33 U6.G35 U6.G37 U6.G39 U6.G41 U6.G43 U6.G45 U6.G47 U6.G49 U6.G51 U6.G53 U6.G55 U6.G57 U6.H23 U6.J23 U6.K23 U6.K57 U6.L22 U6.M23 U6.M57 U6.P57 U6.U57 U6.W57
+VCCIO_OUT: R36.1 U6.A59
+VCCIOA_OUT: R358.1 U6.E20
+VCCPDSW: C230.1 C231.2 R407.1 R408.1 U6.AH10
+VCCRTCEXT: C218.1 U6.AE7
AGND_ADO: C108.2 C123.2 C133.2 C135.2 C141.2 C144.2 C146.2 C147.2 C373.2 C374.2 C379.2 C382.2 C396.2 C398.2 CN6.5 CN6.7 D10.2 D11.2 D12.2 D13.2 Q23.1 Q23.4 R230.2 R288.2 R289.2 R292.1 R296.2 R304.2 R316.2 R320.2 R321.2 R546.1 R553.1 U16.25 U16.38
AGND_CPU: PC2.2 PC7.2 PC8.2 PC9.2 PC11.2 PC71.2 PC72.2 PC74.2 PR1.1 PR2.1 PR4.2 PR6.2 PR7.1 PR80.2 PR81.2 PR84.1 PR85.2 PR86.2 PR87.2 PR94.2 PU7.29 PU7.33 PU7.34 PU7.35 PU7.36 PU7.37 PU7.38 PU7.39 PU7.40 PU7.41 PU7.42
AGND_DDR: PC46.2 PC48.2 PC54.2 PR24.2 PR28.1 PR39.1 PR43.2 PU4.7 PU4.21 PU4.22 PU4.23 PU4.24 PU4.25 PU4.26
GND: BT1.2 C1.1 C2.2 C3.2 C4.2 C5.2 C6.2 C7.2 C8.2 C9.2 C10.2 C11.2 C12.2 C13.2 C14.2 C15.2 C16.2 C17.2 C20.2 C21.2 C22.2 C23.2 C24.2 C25.2 C27.2 C31.2 C32.2 C33.2 C43.2 C44.2 C45.2 C47.2 C49.2 C50.2 C52.2 C55.2 C56.2 C57.2 C58.2 C59.2 C60.2 C61.2 C62.2 C63.2 C64.2 C65.1 C66.1 C67.2 C68.2 C69.1 C70.2 C71.2 C72.2 C73.2 C74.2 C75.2 C76.2 C77.2 C78.2 C79.2 C80.2 C81.2 C82.2 C83.2 C84.2 C85.2 C86.2 C87.2 C88.2 C89.2 C90.2 C91.2 C92.2 C93.2 C94.2 C95.2 C96.2 C97.2 C98.2 C99.2 C100.2 C101.2 C102.2 C103.1 C104.2 C105.2 C106.2 C107.2 C108.1 C109.2 C110.2 C111.2 C112.2 C113.2 C114.2 C115.2 C116.2 C117.2 C118.2 C119.2 C120.2 C124.2 C125.2 C126.2 C127.2 C128.2 C129.2 C131.2 C132.2 C133.1 C134.2 C137.2 C138.2 C139.2 C140.2 C142.2 C143.2 C145.2 C150.2 C151.2 C152.2 C153.2 C154.2 C155.2 C156.2 C157.2 C158.2 C159.2 C160.2 C161.2 C162.2 C163.2 C164.2 C165.2 C166.2 C167.2 C168.2 C169.2 C170.2 C171.2 C172.2 C173.2 C174.2 C175.2 C176.2 C177.2 C178.2 C179.2 C180.2 C181.2 C182.2 C183.2 C184.2 C185.2 C186.2 C187.2 C188.2 C189.2 C190.2 C191.2 C192.2 C193.2 C194.2 C195.2 C196.2 C197.2 C198.2 C199.2 C200.2 C201.2 C202.2 C203.2 C204.2 C205.2 C206.2 C207.2 C208.2 C209.2 C210.2 C211.2 C212.2 C213.2 C214.2 C215.2 C216.2 C217.2 C218.2 C219.2 C220.2 C221.2 C222.2 C223.2 C224.2 C225.2 C226.2 C227.2 C228.2 C229.2 C230.2 C232.2 C233.2 C234.2 C236.2 C238.2 C239.2 C240.2 C241.2 C242.2 C243.2 C244.2 C245.2 C246.2 C247.2 C249.2 C250.2 C251.2 C252.2 C253.2 C254.2 C255.2 C257.2 C258.2 C259.2 C261.2 C262.2 C263.2 C264.2 C265.2 C268.2 C270.2 C271.2 C272.2 C273.2 C274.2 C276.2 C277.2 C278.2 C279.2 C280.2 C281.2 C282.2 C283.2 C284.2 C285.2 C286.2 C287.2 C288.2 C289.2 C290.2 C292.2 C293.1 C294.2 C295.2 C296.2 C297.2 C298.2 C300.2 C301.2 C302.2 C303.2 C305.2 C306.2 C307.2 C308.2 C309.2 C311.2 C312.2 C313.2 C315.2 C316.2 C317.2 C318.2 C319.2 C320.2 C321.2 C322.2 C323.2 C324.2 C325.2 C326.2 C327.2 C328.2 C329.2 C330.2 C331.2 C332.2 C333.2 C334.2 C335.2 C336.2 C337.2 C338.2 C339.2 C340.2 C341.2 C342.2 C343.2 C344.2 C345.2 C346.2 C347.2 C348.2 C349.2 C350.2 C351.2 C352.2 C353.2 C354.2 C355.2 C356.2 C357.2 C358.2 C359.2 C360.2 C361.2 C362.2 C363.2 C364.2 C365.2 C366.2 C367.2 C368.2 C369.2 C371.2 C375.2 C376.2 C378.2 C380.2 C381.2 C383.2 C385.2 C386.2 C388.2 C389.2 C390.2 C393.2 C394.2 C404.2 C405.2 C406.2 C407.2 C408.2 C409.2 C410.2 C712.2 C713.2 C714.2 CLIP1.1 CLIP1.2 CLIP1.3 CLIP2.1 CLIP2.2 CLIP2.3 CLIP3.1 CLIP3.2 CLIP3.3 CLIP4.1 CLIP4.2 CLIP4.3 CLIP5.1 CLIP5.2 CLIP5.3 CLIP6.1 CLIP6.2 CLIP6.3 CLIP7.1 CLIP7.2 CLIP7.3 CLIP8.1 CLIP8.2 CLIP8.3 CLIP9.1 CLIP9.2 CLIP9.3 CLIP10.1 CLIP10.2 CLIP10.3 CLIP11.1 CLIP11.2 CLIP11.3 CLIP12.1 CLIP13.1 CN1.1 CN1.6 CN1.12 CN1.15 CN1.18 CN1.21 CN1.24 CN1.27 CN1.30 CN1.31 CN1.34 CN1.37 CN1.40 CN1.43 CN1.46 CN1.49 CN1.55 CN1.60 CN2.2 CN2.5 CN2.8 CN2.11 CN2.17 CN2.20 CN2.21 CN2.22 CN2.23 CN3.3 CN3.5 CN3.6 CN4.4 CN4.7 CN4.10 CN4.11 CN4.12 CN4.13 CN5.4 CN5.7 CN5.10 CN5.11 CN5.12 CN5.13 CN7.8 CN7.11 CN7.14 CN7.17 CN7.20 CN7.21 CN7.22 CN7.23 CN7.24 CN8.8 CN8.9 CN8.11 CN8.12 CN8.16 CN8.19 CN8.22 CN8.25 CN8.28 CN8.31 CN8.32 CN9.1 CN9.7 CN9.18 CN9.33 CN9.39 CN9.45 CN9.51 CN9.57 CN9.63 CN9.69 CN9.75 CN10.1 CN10.3 CN10.9 CN10.15 CN10.21 CN10.27 CN10.33 CN10.39 CN10.45 CN10.51 CN10.57 CN10.71 CN10.73 CN10.75 CN10.76 CN10.77 CN11.8 CN11.10 CN11.12 CN11.14 CN12.11 CN12.12 CN12.13 CN12.15 CN12.18 CN12.21 CN12.24 CN13.1 CN13.3 CN13.9 CN13.15 CN13.21 CN13.27 CN13.33 CN13.39 CN13.45 CN13.51 CN13.57 CN13.71 CN13.73 CN13.75 CN13.76 CN13.77 CN14.8 CN14.11 CN14.12 CN15.4 CN15.9 CN15.10 CN16.25 CN16.26 CN17.4 CN17.5 CN17.6 CN18.8 CN18.9 CN18.10 CN19.5 CN19.6 CP1.1 CP1.3 CP1.5 CP1.7 CP2.1 CP2.3 CP2.5 CP2.7 CP3.1 CP3.3 CP3.5 CP3.7 CP4.1 CP4.3 CP4.5 CP4.7 CP5.1 CP5.3 CP5.5 CP5.7 CP6.1 CP6.3 CP6.5 CP6.7 D1.2 D5.1 D6.2 D16.2 D17.2 D18.2 D19.2 D20.2 D21.2 D22.2 D23.2 D29.2 D30.2 D31.2 D33.2 D34.2 D35.2 HE1.3 HOLE1.1 HOLE2.1 HOLE4.1 HOLE8.1 HOLE11.1 HOLE11.2 HOLE11.3 HOLE12.1 HOLE13.1 HOLE14.1 HOLE15.1 J2.2 L18.2 PC1.1 PC3.1 PC5.1 PC6.1 PC10.2 PC12.2 PC13.2 PC14.2 PC15.2 PC16.2 PC17.2 PC18.1 PC19.1 PC20.1 PC21.1 PC22.2 PC23.2 PC24.1 PC25.1 PC26.1 PC27.1 PC28.1 PC29.1 PC30.1 PC31.1 PC32.1 PC33.2 PC34.1 PC35.1 PC36.1 PC37.1 PC38.1 PC40.1 PC43.1 PC47.1 PC49.1 PC51.2 PC52.2 PC53.2 PC55.1 PC57.1 PC58.1 PC59.2 PC60.2 PC61.2 PC63.1 PC64.1 PC65.2 PC66.1 PC68.2 PC69.2 PC70.2 PC75.2 PC76.2 PC78.1 PC80.1 PC81.1 PC82.2 PC83.2 PC84.1 PC85.1 PC86.1 PC87.1 PC88.1 PC89.1 PC90.1 PC91.2 PC92.1 PC93.2 PC94.2 PC95.2 PC96.1 PC98.2 PC100.1 PC101.2 PC102.1 PC103.2 PC104.1 PC105.2 PC106.2 PC107.2 PC111.1 PC112.1 PC113.1 PC114.2 PC115.1 PC116.1 PC117.1 PC118.2 PC119.2 PC120.1 PC121.2 PC122.1 PC123.1 PC124.2 PC125.2 PC126.2 PC127.1 PC128.1 PC130.1 PC131.2 PC132.2 PC133.1 PC134.1 PC135.1 PD4.2 PJ1.1 PJ1.2 PJ1.5 PJ1.6 PJ2.1 PJ2.2 PJ2.9 PJ2.10 PQ1.1 PQ1.2 PQ1.3 PQ3.1 PQ5.1 PQ5.2 PQ5.3 PQ6.1 PQ7.1 PQ8.4 PQ9.1 PQ10.1 PQ11.1 PQ13.1 PQ14.1 PQ15.1 PQ16.1 PQ17.1 PQ18.1 PQ19.1 PQ20.1 PQ21.1 PQ22.1 PQ23.1 PQ24.1 PQ29.1 PQ32.1 PQ33.1 PQ37.1 PQ37.4 PQ39.1 PQ39.2 PQ39.3 PR1.2 PR29.2 PR33.2 PR43.1 PR48.2 PR57.1 PR58.1 PR59.1 PR60.2 PR65.1 PR72.1 PR96.1 PR106.2 PR114.2 PR121.2 PR123.2 PR124.2 PR128.2 PR134.2 PR140.2 PR142.2 PR148.2 PR153.2 PR158.1 PR168.1 PU1.3 PU1.9 PU2.2 PU3.2 PU4.4 PU4.10 PU5.11 PU5.12 PU5.13 PU5.14 PU5.15 PU5.16 PU6.2 PU8.8 PU8.9 PU9.4 PU9.5 PU9.6 PU10.8 PU10.9 PU11.14 PU11.21 PU11.22 PU11.23 PU11.24 PU11.25 Q3.2 Q4.1 Q5.1 Q5.4 Q9.1 Q14.1 Q15.1 Q16.1 Q24.1 Q54.1 Q55.1 Q56.1 R23.1 R28.2 R32.1 R33.1 R34.1 R39.1 R58.1 R66.1 R71.1 R89.1 R94.1 R96.1 R100.1 R103.1 R104.1 R105.1 R106.1 R111.2 R112.1 R117.1 R118.1 R137.1 R138.1 R147.1 R149.1 R152.1 R161.1 R169.1 R172.1 R186.1 R187.1 R189.1 R191.1 R192.1 R201.1 R204.1 R206.1 R217.1 R218.1 R219.1 R221.1 R222.1 R223.1 R230.1 R288.1 R289.1 R291.1 R300.1 R301.1 R316.1 R318.1 R320.1 R321.1 R331.1 R335.1 R338.2 R349.1 R360.1 R364.1 R395.2 R413.1 R421.2 R436.1 R437.1 R438.2 R439.2 R440.2 R441.1 R442.1 R443.1 R444.1 R467.1 R471.1 R477.1 R480.1 R484.2 R507.1 R508.1 R514.2 R515.2 R520.1 R523.1 R531.2 R535.1 R543.2 R782.2 R786.2 SW1.4 SW1.5 SW1.6 SW2.3 U1.3 U2.3 U3.3 U4.7 U4.15 U5.2 U5.5 U6.A11 U6.A14 U6.A18 U6.A24 U6.A28 U6.A32 U6.A36 U6.A40 U6.A44 U6.A48 U6.A52 U6.A56 U6.AA1 U6.AA58 U6.AB7 U6.AB10 U6.AB20 U6.AB22 U6.AC61 U6.AD3 U6.AD21 U6.AD63 U6.AE5 U6.AE10 U6.AE58 U6.AF11 U6.AF12 U6.AF14 U6.AF15 U6.AF17 U6.AF18 U6.AG1 U6.AG11 U6.AG21 U6.AG23 U6.AG60 U6.AG61 U6.AG62 U6.AG63 U6.AH16 U6.AH17 U6.AH19 U6.AH20 U6.AH22 U6.AH24 U6.AH28 U6.AH30 U6.AH32 U6.AH34 U6.AH36 U6.AH38 U6.AH40 U6.AH42 U6.AH44 U6.AH46 U6.AH49 U6.AH51 U6.AH53 U6.AH55 U6.AH57 U6.AJ13 U6.AJ14 U6.AJ23 U6.AJ25 U6.AJ27 U6.AJ29 U6.AJ35 U6.AJ39 U6.AJ41 U6.AJ43 U6.AJ45 U6.AJ47 U6.AJ50 U6.AJ52 U6.AJ54 U6.AJ56 U6.AJ58 U6.AJ60 U6.AJ63 U6.AK3 U6.AK23 U6.AK52 U6.AL10 U6.AL13 U6.AL17 U6.AL20 U6.AL22 U6.AL23 U6.AL26 U6.AL29 U6.AL31 U6.AL33 U6.AL36 U6.AL39 U6.AL40 U6.AL45 U6.AL46 U6.AL51 U6.AL52 U6.AL54 U6.AL57 U6.AL60 U6.AL61 U6.AM1 U6.AM17 U6.AM23 U6.AM31 U6.AM52 U6.AN7 U6.AN17 U6.AN23 U6.AN31 U6.AN32 U6.AN35 U6.AN36 U6.AN39 U6.AN40 U6.AN42 U6.AN43 U6.AN45 U6.AN46 U6.AN48 U6.AN49 U6.AN51 U6.AN52 U6.AN60 U6.AN63 U6.AP3 U6.AP10 U6.AP17 U6.AP20 U6.AP22 U6.AP23 U6.AP26 U6.AP29 U6.AP31 U6.AP38 U6.AP39 U6.AP48 U6.AP52 U6.AP54 U6.AP57 U6.AR5 U6.AR11 U6.AR15 U6.AR17 U6.AR23 U6.AR31 U6.AR33 U6.AR39 U6.AR43 U6.AR49 U6.AR52 U6.AT13 U6.AT35 U6.AT37 U6.AT40 U6.AT42 U6.AT43 U6.AT46 U6.AT49 U6.AT61 U6.AT62 U6.AT63 U6.AU1 U6.AU16 U6.AU18 U6.AU20 U6.AU22 U6.AU24 U6.AU26 U6.AU28 U6.AU30 U6.AU33 U6.AU51 U6.AU53 U6.AU55 U6.AU57 U6.AU59 U6.AV8 U6.AV14 U6.AV16 U6.AV20 U6.AV24 U6.AV28 U6.AV33 U6.AV34 U6.AV36 U6.AV39 U6.AV41 U6.AV43 U6.AV46 U6.AV49 U6.AV51 U6.AV55 U6.AV59 U6.AW4 U6.AW16 U6.AW24 U6.AW33 U6.AW35 U6.AW37 U6.AW40 U6.AW42 U6.AW44 U6.AW47 U6.AW50 U6.AW51 U6.AW59 U6.AW60 U6.AY4 U6.AY6 U6.AY11 U6.AY16 U6.AY18 U6.AY22 U6.AY24 U6.AY26 U6.AY30 U6.AY33 U6.AY51 U6.AY53 U6.AY57 U6.AY59 U6.B4 U6.B20 U6.B24 U6.B26 U6.B28 U6.B32 U6.B36 U6.B40 U6.B44 U6.B48 U6.B52 U6.B56 U6.B60 U6.C11 U6.C14 U6.C18 U6.C20 U6.C25 U6.C27 U6.C38 U6.C39 U6.C57 U6.D2 U6.D5 U6.D8 U6.D12 U6.D14 U6.D18 U6.D21 U6.D23 U6.D25 U6.D26 U6.D27 U6.D29 U6.D30 U6.D31 U6.D33 U6.D34 U6.D35 U6.D37 U6.D38 U6.D39 U6.D41 U6.D42 U6.D43 U6.D45 U6.D46 U6.D47 U6.D49 U6.D50 U6.D51 U6.D53 U6.D54 U6.D55 U6.D57 U6.D59 U6.D62 U6.D63 U6.E11 U6.E17 U6.F20 U6.F26 U6.F30 U6.F34 U6.F38 U6.F42 U6.F46 U6.F50 U6.F54 U6.F58 U6.F61 U6.G3 U6.G5 U6.G6 U6.G8 U6.G18 U6.G22 U6.H13 U6.H17 U6.H57 U6.J10 U6.J22 U6.J59 U6.J63 U6.K1 U6.K12 U6.L7 U6.L13 U6.L15 U6.L17 U6.L18 U6.L20 U6.L58 U6.L61 U6.M22 U6.N3 U6.N10 U6.N21 U6.P22 U6.P59 U6.P62 U6.P63 U6.R8 U6.R10 U6.R22 U6.T1 U6.T58 U6.U9 U6.U20 U6.U22 U6.U61 U6.V3 U6.V7 U6.V10 U6.V23 U6.V58 U6.W20 U6.W22 U6.Y10 U6.Y59 U6.Y63 U7.3 U8.1 U9.4 U10.1 U11.B2 U11.B5 U11.B6 U11.B12 U11.C3 U11.C5 U11.C6 U11.D3 U11.D8 U11.D12 U11.E4 U11.E5 U11.E6 U11.F4 U11.F5 U11.F6 U11.F12 U11.G3 U11.G4 U11.G6 U11.G8 U11.G9 U11.H2 U11.H10 U11.J4 U11.J12 U11.K2 U11.K10 U11.L6 U11.L8 U11.L9 U11.M4 U11.M5 U11.M6 U11.M12 U11.N4 U11.N5 U11.N6 U11.P3 U11.P8 U11.P12 U11.R4 U11.R5 U11.R6 U11.T2 U11.T3 U11.T4 U11.T5 U11.T6 U11.T12 U12.B2 U12.B5 U12.B6 U12.B12 U12.C3 U12.C5 U12.C6 U12.D3 U12.D8 U12.D12 U12.E4 U12.E5 U12.E6 U12.F4 U12.F5 U12.F6 U12.F12 U12.G3 U12.G4 U12.G6 U12.G8 U12.G9 U12.H2 U12.H10 U12.J4 U12.J12 U12.K2 U12.K10 U12.L6 U12.L8 U12.L9 U12.M4 U12.M5 U12.M6 U12.M12 U12.N4 U12.N5 U12.N6 U12.P3 U12.P8 U12.P12 U12.R4 U12.R5 U12.R6 U12.T2 U12.T3 U12.T4 U12.T5 U12.T6 U12.T12 U13.B2 U13.B5 U13.B6 U13.B12 U13.C3 U13.C5 U13.C6 U13.D3 U13.D8 U13.D12 U13.E4 U13.E5 U13.E6 U13.F4 U13.F5 U13.F6 U13.F12 U13.G3 U13.G4 U13.G6 U13.G8 U13.G9 U13.H2 U13.H10 U13.J4 U13.J12 U13.K2 U13.K10 U13.L6 U13.L8 U13.L9 U13.M4 U13.M5 U13.M6 U13.M12 U13.N4 U13.N5 U13.N6 U13.P3 U13.P8 U13.P12 U13.R4 U13.R5 U13.R6 U13.T2 U13.T3 U13.T4 U13.T5 U13.T6 U13.T12 U14.B2 U14.B5 U14.B6 U14.B12 U14.C3 U14.C5 U14.C6 U14.D3 U14.D8 U14.D12 U14.E4 U14.E5 U14.E6 U14.F4 U14.F5 U14.F6 U14.F12 U14.G3 U14.G4 U14.G6 U14.G8 U14.G9 U14.H2 U14.H10 U14.J4 U14.J12 U14.K2 U14.K10 U14.L6 U14.L8 U14.L9 U14.M4 U14.M5 U14.M6 U14.M12 U14.N4 U14.N5 U14.N6 U14.P3 U14.P8 U14.P12 U14.R4 U14.R5 U14.R6 U14.T2 U14.T3 U14.T4 U14.T5 U14.T6 U14.T12 U15.4 U15.11 U15.18 U15.25 U16.4 U16.49 U17.9 U18.3 U19.4 U20.3 U21.3 U22.1 U23.1 U23.27 U23.49 U23.91 U23.113 U23.122 Y1.2 Y1.4
VCC_SENSE: PC76.1 PR100.2 PR104.1 R38.1 U6.E63
VCCST_PWRGD: C20.1 R7.1 R8.2 U1.2 U6.B59
VCCST_PWRGD_EN: R9.2 R13.2 R16.2 U3.2
VCCST_PWRGD_R: R7.2 U3.4
VCCST_PWRGD_XDP: CN1.50 R6.2
VIN: JP3.2 JP4.2 JP5.2 JP6.2 PC1.2 PC3.2 PC5.2 PC6.2 PC13.1 PC107.1 PC119.1 PC120.2 PC130.2 PC131.1 PD2.2 PQ36.1 PQ36.2 PQ36.3 PQ38.5 PR30.1 PR47.1 PR52.1 PR55.1 PR79.1 PR82.1 PR119.1 PR129.1 PR150.2 PR151.2 PR154.1 PU1.5 R143.1 R150.1 R785.1
VSS_SENSE: PC75.1 PR96.2 PR98.2 R26.2
VSS_SENSE_R: R26.1 R39.2 U6.E62
2ND_MBCLK: Q11.3 Q17.3 R139.2 R511.1 R554.2 U23.115
2ND_MBDATA: Q11.6 Q17.6 R135.2 R512.1 R555.2 U23.116
670_BST: PR20.1 PU3.10
670_BST1: PC42.1 PR20.2
670_CLK: PC108.2 PC109.2 PC110.2 PU3.5
670_EN: PC50.2 PR37.1 PR45.2 PU3.13
670_ENLDO: PR35.2 PU3.12
670_SW: PC42.2 PL4.1 PR138.1 PU3.8 PU3.9 PU3.15 PU3.16
670PG: PR40.1 PU3.4
671_BST: PR21.1 PU2.10
671_BST1: PC41.1 PR21.2
671_EN: PC99.2 PR32.1 PR41.2 PU2.13
671_FB: PR137.2 PR139.1 PU2.12
671_SW: PC41.2 PL3.1 PR135.1 PU2.8 PU2.9 PU2.15 PU2.16
671PG: PR22.1 PU2.4
24707_LX: PC129.1 PL10.2 PQ38.1 PQ38.2 PQ38.3 PQ39.5 PR75.1 PU11.19
24737_ACDET: PR72.2 PR73.2 PU11.6
24737_ACN: PC65.1 PC67.2 PR151.1 PU11.1
24737_ACP: PC66.2 PC67.1 PR146.1 PU11.2
24737_BM#: PQ16.2 PR170.1 PU11.11
24737_BST: PR163.2 PU11.17
24737_CMPIN: PR68.2 PR157.1 PR158.2 PU11.4
24737_CMPOUT: PQ15.2 PR156.1 PR157.2 PR176.2 PU11.3
24737_DH: PQ38.4 PU11.18
24737_DL: PQ39.4 PU11.15
24737_ILIM: PC133.2 PR167.1 PR168.2 PR169.2 PU11.10
24737_REGN: PC132.1 PD8.2 PU11.16
24737_SRN: PC135.2 PC136.1 PR172.1 PR174.1
24737_SRP: PC134.2 PC136.2 PR171.1 PR173.1
24737_VCC: PC127.2 PR67.2 PU11.20
51216_DRVH: PQ2.4 PU4.14
51216_DRVL: PQ1.4 PU4.11
51216_MODE: PR39.2 PU4.19
51216_REF: PC48.1 PR19.1 PU4.6
51216_REFIN: PC46.1 PR19.2 PR24.1 PU4.8
51216_S3: PR25.2 PR27.2 PR36.2 PU4.17
51216_S5: PR23.2 PR25.1 PU4.16
51216_SW: PC39.2 PL2.1 PQ1.5 PQ2.1 PQ2.2 PQ2.3 PR16.1 PU4.13
51216_TRIP: PR28.2 PU4.18
51216_VBST: PR18.1 PU4.15
51624_ALERT#: PR109.2 PU7.32
51624_B-RAMP: PR78.2 PR87.1 PU7.11
51624_CLK: PR110.2 PU7.31
51624_COMP: PC79.2 PR107.2 PR111.2 PR112.1 PU7.26
51624_CSN1: PC73.2 PC74.1 PR14.2 PR15.1 PR91.2 PU7.18
51624_CSN2: PR94.1 PU7.19
51624_CSP1: PC72.1 PC73.1 PR12.2 PR13.1 PR91.1 PU7.17
51624_CSP2: PR97.1 PU7.20
51624_DATA: PR108.2 PU7.1
51624_DROOP: PC77.1 PC79.1 PR111.1 PU7.25
51624_F-IMAX: PR77.2 PR86.1 PU7.10
51624_GFB: PR98.1 PU7.23
51624_IMON: PC71.1 PR89.1 PU7.13
51624_MODE: PR7.2 PU7.4
51624_O-USR: PR76.2 PR85.1 PU7.9
51624_OCP-I: PR81.1 PR88.2 PR89.2 PU7.12
51624_PWM1: PU1.8 PU7.6
51624_PWM2: PR6.1 PU7.5
51624_SKIP#: PR95.1 PU1.1 PU7.7
51624_SLEWA: PR3.2 PR4.1 PU7.15
51624_THERM: PC2.1 PR2.2 PR11.1 PU7.14
51624_V5A: PC8.1 PR9.1 PU7.28
51624_VBAT: PR82.2 PU7.16
51624_VDD: PC7.1 PR105.1 PU7.2
51624_VFB: PR100.1 PU7.24
51624_VREF: PC9.1 PR3.1 PR11.2 PR76.1 PR77.1 PR78.1 PR107.1 PU7.27
51624_VRON: PR83.2 PR84.2 PR90.2 PR92.1 PU7.8
51716_VIN: JP3.1 PC33.1 PC34.2 PC91.1 PQ2.5
+DDR_VTT_RUN: C102.1 C107.1 C110.1 C111.1 C112.1 C113.1 C115.1 C116.1 C117.1 C118.1 C119.1 C125.1 C126.1 C127.1 C128.1 C129.1 PC59.1 PC60.1 PU4.1 PU4.3 R207.1 R209.1 R211.1 R212.1 R215.1 R216.1 R231.1 R232.1 R233.1 R234.1 R235.1 R236.1 R237.1 R238.1 R239.1 R240.1 R241.1 R242.1 R243.1 R244.1 R245.1 R246.1 R247.1 R248.1 R249.1 R250.1 R251.1 R252.1 R253.1 R254.1 R255.1 R256.1 R257.1 R258.1 R259.1 R260.1 R261.1 R262.1 R263.1 R264.1 R265.1 R266.1 R267.1 R268.1 R269.1 R270.1 R271.1 R272.1 R273.1 R274.1 R275.1 R276.1 R277.1 R278.1 R279.1 R280.1 R281.1 R282.1 R283.1 R284.1 R285.1 R286.1
+M_VREF_CA: C304.1 R521.2 U6.AP49
+M_VREF_DQ0: C260.1 R472.2 U6.AR51
+M_VREF_DQ1: C256.1 R468.2 U6.AP51
+PCH_VCCDSW: C228.1 C231.1 U6.AG19 U6.AG20
+SM_VREF_CA: C94.1 C97.1 C104.1 C105.1 C106.1 C109.1 C316.1 C340.1 C349.1 R521.1 R523.2 R524.1 U11.H4 U12.H4 U13.H4 U14.H4
+SM_VREF_DQA: C262.1 C287.1 C288.1 C297.1 C298.1 R472.1 R479.1 R480.2 U13.J11 U14.J11
+SM_VREF_DQB: C261.1 C281.1 C283.1 C295.1 C296.1 R468.1 R476.1 R477.2 U11.J11 U12.J11
+TPVDD: C160.1 C712.1 CN15.1 Q53.3 R323.2 R568.1 R569.1 R575.2 R576.2 R580.2 R784.1
AC_PROTECT: PR176.1 U23.85
ACIN: PQ37.3 PR155.1 U23.72
ACPRESENT: PR161.1 PR165.2 R416.1
AMP_MUTE#: D15.1 U23.108
APS1: CN11.1 R195.2 R198.2
APS2: CN11.2 R500.2
APS3: CN11.3 R194.2 R197.2 R198.1
APS4: CN11.4 R499.2
APS5: CN11.5 R498.2
APS6: CN11.6 R497.2
APS7: CN11.7 R196.2 R197.1
APS9: CN11.9 R496.2
APS11: CN11.11 R495.2
APS13: CN11.13 R494.2
APS15: CN11.15 R493.2
APWORK: R9.1 R394.2 U23.68
APWROK_R: R393.1 R394.1 R395.1 U6.AB5
BAT-V: PC123.2 PC124.1 PC125.1 PL8.2 PL9.2 PQ36.5 PR159.2 PR174.2
BATLED0#: CN18.6 U23.29
BATLED1#: CN18.7 U23.25
BC_CEN: R490.2 U17.1 U21.2
BKLEN: Q5.5 R331.2 R340.1 R341.1
BL#: Q5.2 Q5.3 R40.1
BOARD_ID0: R70.2 R71.2 U6.P1
BOARD_ID1: R362.2 R364.2 U6.R5
BOARD_ID2: R63.2 R66.2 U6.L4
BOARD_ID3: R22.2 R23.2 U6.C4
BOARD_ID4: R58.2 R60.2 U6.L3
BT_EN: CN9.54 U23.104
CATERR#: TP10.1 U6.K61
CFG0: CN1.35 R106.2 U6.AC60
CFG1: CN1.36 R105.2 U6.AC62
CFG2: CN1.38 U6.AC63
CFG3: CN1.39 R104.2 U6.AA63
CFG4: CN1.44 R103.2 U6.AA60
CFG5: CN1.45 U6.Y62
CFG6: CN1.47 U6.Y61
CFG7: CN1.48 U6.Y60
CFG8: CN1.26 R100.2 U6.V62
CFG9: CN1.25 R112.2 U6.V61
CFG10: CN1.23 R96.2 U6.V60
CFG11: CN1.22 U6.U60
CFG12: CN1.17 U6.T63
CFG13: CN1.16 U6.T62
CFG14: CN1.14 U6.T61
CFG15: CN1.13 U6.T60
CFG_RCOMP: R111.1 U6.V63
CLK_PCH_PCI3: R188.2 R454.2 U6.AN15
CLK_PCH_PCI4: R460.2 U6.AP15
CLK_PCI_EC: C258.1 R460.1 R530.2 U23.13
CLK_PCI_LPC: C257.1 CN14.6 R454.1 R561.2
CLK_PCI_LPC_C: CN9.71 R561.1
CLK_PCI_TPM: C72.1 R188.1 U15.21
CLK_PCIE_NGFF0_N: CN13.53 U6.A39
CLK_PCIE_NGFF0_P: CN13.55 U6.B39
CLK_PCIE_NGFF1_N: CN10.53 U6.B37
CLK_PCIE_NGFF1_P: CN10.55 U6.A37
CLK_PCIE_REQ0#: R76.1 U6.U2
CLK_PCIE_REQ1#: R93.1 U6.Y5
CLK_PCIE_REQ2#: R99.1 U6.AD1
CLK_PCIE_WLAN_N: CN9.49 U6.B38
CLK_PCIE_WLAN_P: CN9.47 U6.C37
CLK_PCIE_XDPN: CN1.10 U6.B35
CLK_PCIE_XDPP: CN1.11 U6.A35
CLK_SCLK: CN1.57 Q10.4 R131.1 R422.2
CLK_SDATA: CN1.56 Q10.1 R121.1 R423.2
CLKRUN#: R225.1 R371.2 U6.V5 U23.93
CN_HDMI_CLKN: C26.2 CN2.12 R59.1 R350.2
CN_HDMI_CLKP: C28.2 CN2.10 R59.2 R354.2
CN_HDMI_TXN0: C29.2 CN2.9 R73.1 R359.2
CN_HDMI_TXN1: C48.2 CN2.6 R110.1 R385.2
CN_HDMI_TXN2: C34.2 CN2.3 R92.1 R373.2
CN_HDMI_TXP0: C30.2 CN2.7 R73.2 R363.2
CN_HDMI_TXP1: C51.2 CN2.4 R110.2 R389.2
CN_HDMI_TXP2: C46.2 CN2.1 R92.2 R380.2
CODEC_SENSEA: R293.2 U16.13
CODEC_VREF: C382.1 U16.28
CPU_DRAMRST#: TP23.1 U6.AV15
CS_BST1: PC4.1 PU1.7
CS_BSTR1: PR5.2 PU1.6
CS_SW1: PL1.1 PR10.1 PU1.4
D/C#: PR34.2 U23.107
DC_TEST_A3_B3: U6.A3 U6.B3
DC_TEST_A61_B61: U6.A61 U6.B61
DC_TEST_AY2_AW2: U6.AW2 U6.AY2
DC_TEST_AY3_AW3: U6.AW3 U6.AY3
DC_TEST_AY61_AW61: U6.AW61 U6.AY61
DC_TEST_AY62_AW62: U6.AW62 U6.AY62
DC_TEST_B62_B63: U6.B62 U6.B63
DC_TEST_C1_C2: U6.C1 U6.C2
DDR_PG_CTRL: U6.AV61 U7.2
DDR_VTTREF: PC54.1 PU4.5
DDR_VTTT_PG_CTRL: PR27.1 R142.2 R779.2 R782.1 U7.4
DEVSLP0: R199.2 R365.2 U6.P2
DEVSLP1: R61.2 R319.2 U6.L2
DEVSLP_N0: CN13.38 R318.2 R319.1
DEVSLP_N1: CN10.38 R199.1 R201.2
DMIC_CLK: R578.2 U16.3
DMIC_CLK_C: CN17.3 R578.1
DMIC_DATA: R577.2 U16.2
DMIC_DATA_C: CN17.2 R577.1
DNBSWON#: R464.1 U23.120
DP_UTIL: R34.2 R35.2 U6.A43
DPWROK: R190.1 U23.124
DPWROK_R: R169.2 R181.1 R190.2 U6.AV5
DSWVREN: R178.1 U6.AW7
EC_FPBACK#: Q4.2 U23.118
EC_PWROK: R107.2 R109.2 R484.1 U20.1 U23.33
EC_PWROK_R: R183.1 R184.1 U6.AY7
ECAGND: C130.2 C370.2 L18.1 U23.75
EDP_AUXN: C53.1 U6.A45
EDP_AUXN_C: C53.2 CN8.17 R128.2 R137.2
EDP_AUXP: C54.1 U6.B45
EDP_AUXP_C: C54.2 CN8.18 R129.2 R138.2
EDP_BKLEN: R340.2 U6.A9
EDP_BKLEN_EC: R341.2 U23.119
EDP_BKLTCL: CN8.6 R35.1 U6.B8
EDP_HPD: CN8.10 R335.2 U6.D6
EDP_RCOMP: R358.2 U6.D20
EDP_TXN0: C41.1 U6.C45
EDP_TXN0_C: C41.2 CN8.21
EDP_TXN1: C39.1 U6.A47
EDP_TXN1_C: C39.2 CN8.24
EDP_TXN2: C37.1 U6.C47
EDP_TXN2_C: C37.2 CN8.27
EDP_TXN3: C35.1 U6.A49
EDP_TXN3_C: C35.2 CN8.30
EDP_TXP0: C42.1 U6.B46
EDP_TXP0_C: C42.2 CN8.20
EDP_TXP1: C40.1 U6.B47
EDP_TXP1_C: C40.2 CN8.23
EDP_TXP2: C38.1 U6.C46
EDP_TXP2_C: C38.2 CN8.26
EDP_TXP3: C36.1 U6.B49
EDP_TXP3_C: C36.2 CN8.29
EDP_VDDEN: R89.2 U5.3 U6.C6
EL_SCL_C: CN12.22 Q17.4 R552.2 R554.1
EL_SDA_C: CN12.23 Q17.1 R555.1 R559.2
FAN_PWM: Q12.1 U23.32
FANSIG: CN3.2 R157.1 U23.47
GPIO2: R48.2 U6.J3
GPIO3: R47.2 U6.J4
GPIO8: R156.2 U6.AU2
GPIO12: R452.2 R777.2 U6.AM7
GPIO15: R403.1 U6.AD6
GPIO17: R374.2 U6.T3
GPIO24: R399.2 U6.AD5
GPIO25: R136.2 R778.2 U6.AM4
GPIO26: R144.2 U6.AN3
GPIO27: R427.2 R776.2 U6.AN5
GPIO28: R391.2 U6.AD7
GPIO44: R113.2 U6.AK4
GPIO46: R98.2 U6.AG3
GPIO47: R383.2 U6.AB6
GPIO48: R81.2 U6.U4
GPIO49: R95.2 U6.Y3
GPIO50: R72.2 U6.P3
GPIO52: R62.1 U6.L1
GPIO56: R406.2 U6.AG6
GPIO57: R146.2 U6.AP1
GPIO58: R425.2 U6.AL4
GPIO59: R451.2 U6.AT5
GPIO64: R19.2 U6.E3
GPIO65: R334.2 U6.F4
GPIO66: R20.1 U6.D3
GPIO67: R330.2 U6.E4
GPIO68: R21.2 U6.C3
GPIO69: R18.2 U6.E2
GPIO84: R344.2 U6.L6
GPIO85: R356.2 U6.N6
GPIO86: R345.1 U6.L8
GPIO87: R361.2 U6.R7
GPIO88: R351.2 U6.L5
GPIO89: R355.2 U6.N7
GPIO90: R46.2 U6.K2
GPIO91: R49.2 U6.J1
GPIO92: R357.2 U6.K3
GPIO93: R50.2 U6.J2
GPIO94: R51.2 U6.G1
H_CPU_SVIDART#: R83.1 U6.L62
H_CPU_SVIDCLK: R91.2 U6.N63
H_CPU_SVIDDAT: R77.2 U6.L63
H_PECI: R513.1 U6.N62
H_PROCHOT#: PQ15.3 PR8.2 PR64.1 PU7.30 Q24.3 R68.2 R69.1
H_PROCHOT#_R: R68.1 U6.K63
H_PWRGOOD: R28.1 U6.C61
H_SYS_PWROK_XDP: CN1.54 R4.2 R5.2
HDA_BCLK_R: R180.1 U6.AW8
HDA_RST#_R: R457.1 U6.AU8
HDA_SDO_R: R456.1 R470.1 U6.AU11
HDA_SYNC_R: C69.2 R185.1 U6.AV11
HDMI_CLKN: C26.1 U6.A57
HDMI_CLKP: C28.1 U6.B57
HDMI_DDCCLK: Q7.1 R53.1 U6.B9
HDMI_DDCCLK_CN: CN2.15 Q7.3 R29.1
HDMI_DDCDAT: Q6.1 R52.1 U6.C9
HDMI_DDCDAT_CN: CN2.16 Q6.3 R27.1
HDMI_HPD: Q18.1 R343.1 U6.C8
HDMI_HPD_CN: CN2.19 R348.2
HDMI_HPD_CN_R: D17.1 Q18.3 R348.1 R349.2
HDMI_TXN0: C29.1 U6.B55
HDMI_TXN1: C48.1 U6.B58
HDMI_TXN2: C34.1 U6.C54
HDMI_TXP0: C30.1 U6.A55
HDMI_TXP1: C51.1 U6.C58
HDMI_TXP2: C46.1 U6.C55
HP_IC_L: C121.2 R302.1 R305.2 U16.32
HP_IC_R: C122.2 R297.1 R309.2 U16.33
HP_L: L7.1 R296.1 R305.1
HP_R: L8.1 R304.1 R309.1
HPL_SYS: C141.1 CN6.1 D11.1 L7.2
HPOUT_JD: CN6.6 R293.1
HPR_SYS: C144.1 CN6.2 D12.1 L8.2
HWPG: D24.2 D25.2 D26.2 D27.2 D28.2 R529.1 U23.84
HWPG_1.2V: D24.1 PR42.1 PU4.20
HWPG_1.5V: D27.1 PR127.1 PU8.1
HWPG_1.05V_S5: D28.1 PR56.1 PU5.1 R6.1 R16.1
HWPG_1.8V: D25.1 PR152.1 PU10.1
I2C_TP_SCL: CN15.6 Q25.6 R571.1 R575.1
I2C_TP_SDA: CN15.5 Q25.3 R576.1 R581.1
I2C_TS_SCL: CN7.10 Q8.6 R398.1 R400.1
I2C_TS_SDA: CN7.9 Q8.3 R388.1 R397.1
ICLK_BIAS: R342.2 U6.C26
ICMNT: C130.1 PC128.2 PR68.1 PU11.7 U23.67
IMVP_PWRGD: PR103.1 R37.1 U2.2 U6.C59
IMVP_PWRGD_3V: Q1.2 R2.2 R193.1 U2.4 U20.2
INT_AMIC-VREFO: C373.1 R546.2 U16.27
IRQ_SERIRQ: R372.2 U6.T4 U15.27 U23.5
L_SPK+: R322.2 U16.42
L_SPK-: R326.2 U16.43
LCD_BL_ON: CN8.7 D4.2 Q4.3 Q5.6 R14.1
LCD_VCC: C52.1 C55.1 C56.1 CN8.13 CN8.14 CN8.15 R102.2
LCD_VCC_S: C33.1 C45.1 R102.1 U5.1
LCD_VIN: C57.1 C59.1 CN8.1 CN8.2 CN8.3 CN8.4 R143.2 R150.2
LID1#: D4.1 D5.2 HE1.2 R45.1 U23.86
LID2#: CN18.3 U23.97
LINE1L-VREFO: R302.2 U16.31
LINE1L_R: C121.1 U16.22
LINE1R-VREFO: R297.2 U16.30
LINE1R_R: C122.1 U16.21
LINE2-L: TP18.1 U16.24
LINE2-R: TP17.1 U16.23
LM393_PIN2: PR17.2 PR132.2 PU9.2
LPC_LAD0: CN14.5 R562.1 U6.AU14 U15.26 U23.10
LPC_LAD0_C: CN9.64 R562.2
LPC_LAD1: CN14.4 R563.1 U6.AW12 U15.23 U23.9
LPC_LAD1_C: CN9.66 R563.2
LPC_LAD2: CN14.3 R564.1 U6.AY12 U15.20 U23.8
LPC_LAD2_C: CN9.68 R564.2
LPC_LAD3: CN14.2 R565.1 U6.AW11 U15.17 U23.7
LPC_LAD3_C: CN9.70 R565.2
LPC_LFRAME#: CN14.1 R566.2 U6.AV12 U15.22 U23.6
LPC_LFRAME#_C: CN9.73 R566.1
MA_AMA0: R258.2 U6.AR36 U14.R2
MA_AMA1: R257.2 U6.AU40 U14.P2
MA_AMA2: R255.2 U6.AV40 U14.N2
MA_AMA3: R256.2 U6.AY39 U14.N3
MA_AMA4: R254.2 U6.AW39 U14.M3
MA_AMA5: R249.2 U6.AY41 U14.F3
MA_AMA6: R247.2 U6.AU41 U14.E3
MA_AMA7: R248.2 U6.AW41 U14.E2
MA_AMA8: R246.2 U6.AU42 U14.D2
MA_AMA9: R245.2 U6.AV42 U14.C2
MA_AZQ0: R218.2 U14.B3
MA_AZQ1: R204.2 U14.B4
MA_BMA0: R244.2 U6.AR35 U13.R2
MA_BMA1: R243.2 U6.AU34 U13.P2
MA_BMA2: R241.2 U6.AW34 U13.N2
MA_BMA3: R242.2 U6.AY34 U13.N3
MA_BMA4: R240.2 U6.AU35 U13.M3
MA_BMA5: R235.2 U6.AR38 U13.F3
MA_BMA6: R233.2 U6.AV35 U13.E3
MA_BMA7: R234.2 U6.AP35 U13.E2
MA_BMA8: R232.2 U6.AY37 U13.D2
MA_BMA9: R231.2 U6.AU36 U13.C2
MA_BZQ0: R222.2 U13.B3
MA_BZQ1: R217.2 U13.B4
MA_CKE0: R253.2 U6.AU43 U14.K3
MA_CKE1: R252.2 U6.AW43 U14.K4
MA_CKE2: R238.2 U6.AY42 U13.K3
MA_CKE3: R239.2 U6.AY43 U13.K4
MA_CLKN0: R251.2 U6.AU37 U14.J2
MA_CLKN1: R237.2 U6.AW36 U13.J2
MA_CLKP0: R250.2 U6.AV37 U14.J3
MA_CLKP1: R236.2 U6.AY36 U13.J3
MA_CS#0: R215.2 U6.AP33 U13.L3 U14.L3
MA_CS#1: R211.2 U6.AR32 U13.L4 U14.L4
MA_DQ0: U6.AH63 U14.R9
MA_DQ1: U6.AH62 U14.T8
MA_DQ2: U6.AK63 U14.T10
MA_DQ3: U6.AK62 U14.T11
MA_DQ4: U6.AH61 U14.R8
MA_DQ5: U6.AH60 U14.T9
MA_DQ6: U6.AK61 U14.R10
MA_DQ7: U6.AK60 U14.R11
MA_DQ8: U6.AM63 U14.M8
MA_DQ9: U6.AM62 U14.N9
MA_DQ10: U6.AP63 U14.N11
MA_DQ11: U6.AP62 U14.M11
MA_DQ12: U6.AM61 U14.M9
MA_DQ13: U6.AM60 U14.P9
MA_DQ14: U6.AP61 U14.M10
MA_DQ15: U6.AP60 U14.N10
MA_DQ16: U6.AP58 U14.E9
MA_DQ17: U6.AR58 U14.D9
MA_DQ18: U6.AM57 U14.F10
MA_DQ19: U6.AK57 U14.F11
MA_DQ20: U6.AL58 U14.E10
MA_DQ21: U6.AK58 U14.E11
MA_DQ22: U6.AR57 U14.F9
MA_DQ23: U6.AN57 U14.F8
MA_DQ24: U6.AP55 U14.B10
MA_DQ25: U6.AR55 U14.C10
MA_DQ26: U6.AM54 U14.B8
MA_DQ27: U6.AK54 U14.C8
MA_DQ28: U6.AL55 U14.B11
MA_DQ29: U6.AK55 U14.C11
MA_DQ30: U6.AR54 U14.B9
MA_DQ31: U6.AN54 U14.C9
MA_DQ32: U6.AY58 U13.R9
MA_DQ33: U6.AW58 U13.T8
MA_DQ34: U6.AY56 U13.T11
MA_DQ35: U6.AW56 U13.T10
MA_DQ36: U6.AV58 U13.R8
MA_DQ37: U6.AU58 U13.T9
MA_DQ38: U6.AV56 U13.R11
MA_DQ39: U6.AU56 U13.R10
MA_DQ40: U6.AY54 U13.M9
MA_DQ41: U6.AW54 U13.N9
MA_DQ42: U6.AY52 U13.N10
MA_DQ43: U6.AW52 U13.N11
MA_DQ44: U6.AV54 U13.P9
MA_DQ45: U6.AU54 U13.M8
MA_DQ46: U6.AV52 U13.M10
MA_DQ47: U6.AU52 U13.M11
MA_DQ48: U6.AK40 U13.C8
MA_DQ49: U6.AK42 U13.B8
MA_DQ50: U6.AM43 U13.C10
MA_DQ51: U6.AM45 U13.B11
MA_DQ52: U6.AK45 U13.C11
MA_DQ53: U6.AK43 U13.B10
MA_DQ54: U6.AM40 U13.C9
MA_DQ55: U6.AM42 U13.B9
MA_DQ56: U6.AM46 U13.E11
MA_DQ57: U6.AK46 U13.F10
MA_DQ58: U6.AM49 U13.E9
MA_DQ59: U6.AK49 U13.F9
MA_DQ60: U6.AM48 U13.F11
MA_DQ61: U6.AK48 U13.E10
MA_DQ62: U6.AM51 U13.D9
MA_DQ63: U6.AK51 U13.F8
MA_DQSN0: U6.AJ61 U14.P11
MA_DQSN1: U6.AN62 U14.L11
MA_DQSN2: U6.AM58 U14.G11
MA_DQSN3: U6.AM55 U14.D11
MA_DQSN4: U6.AV57 U13.P11
MA_DQSN5: U6.AV53 U13.L11
MA_DQSN6: U6.AL43 U13.D11
MA_DQSN7: U6.AL48 U13.G11
MA_DQSP0: U6.AJ62 U14.P10
MA_DQSP1: U6.AN61 U14.L10
MA_DQSP2: U6.AN58 U14.G10
MA_DQSP3: U6.AN55 U14.D10
MA_DQSP4: U6.AW57 U13.P10
MA_DQSP5: U6.AW53 U13.L10
MA_DQSP6: U6.AL42 U13.D10
MA_DQSP7: U6.AL49 U13.G10
